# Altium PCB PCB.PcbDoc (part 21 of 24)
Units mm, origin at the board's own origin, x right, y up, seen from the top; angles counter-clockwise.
Board outline 100 x 160 mm, 10 copper layers (TOP_L1, L2, L3, L4, L5, L6, L7, L8, L9, BOTTOM_L10), stack 1.946 mm thick; 1358 components, 1149 nets, 6777 pads, 10914 vias.
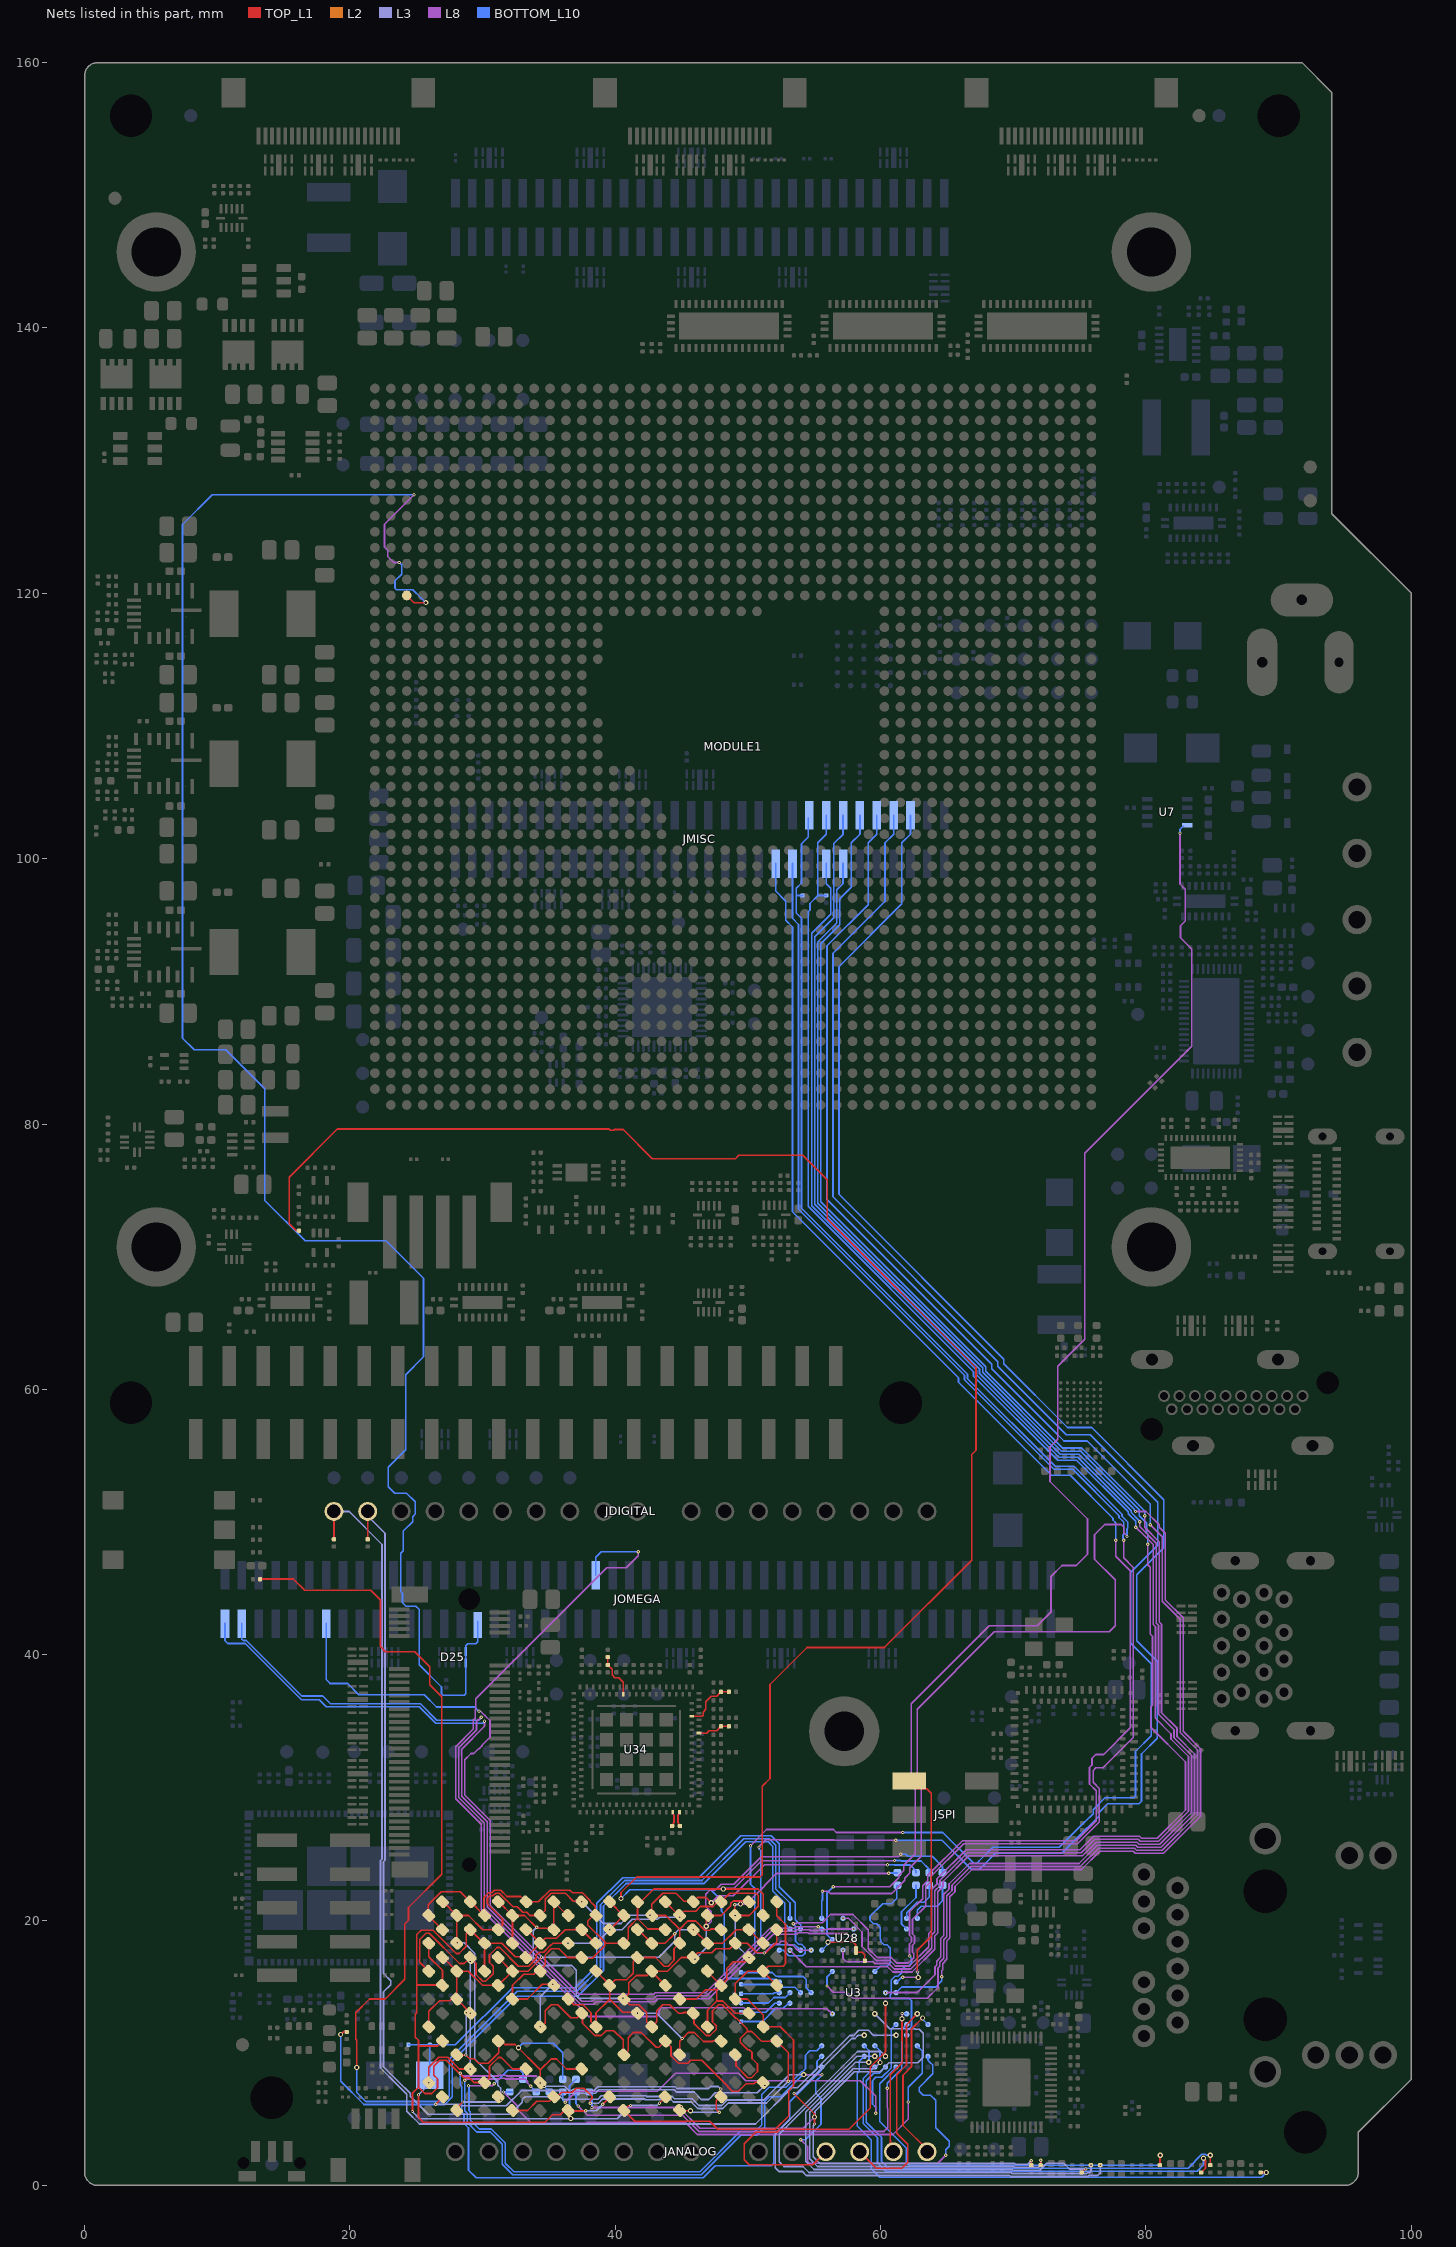
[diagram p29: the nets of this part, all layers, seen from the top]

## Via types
v1: diameter 0.25, hole 0.1, TOP_L1 to L2, tented both sides, 3439 vias
v2: diameter 0.25, hole 0.1, L2 to L3, tented both sides, 2256 vias
v3: diameter 0.25, hole 0.1, L9 to BOTTOM_L10, tented both sides, 1685 vias
v4: diameter 0.25, hole 0.1, L8 to L9, tented both sides, 1675 vias
v5: diameter 0.4, hole 0.2, L3 to L8, tented both sides, 1251 vias
v6: diameter 0.6, hole 0.3, TOP_L1 to BOTTOM_L10, tented both sides, 600 vias
v7: diameter 0.24, hole 0.1, TOP_L1 to L2, tented both sides, 8 vias

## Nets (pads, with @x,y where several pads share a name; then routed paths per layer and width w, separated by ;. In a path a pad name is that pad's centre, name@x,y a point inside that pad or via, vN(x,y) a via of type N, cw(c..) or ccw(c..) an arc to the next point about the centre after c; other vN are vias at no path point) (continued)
PE4: JMISC.6 U3.C4 | length 132.4
  L8 w0.127: v3(50.834,25.477) 50.834,25.51 50.898,25.574 50.898,25.596 51.345,26.043 52.351,26.043 52.362,26.031 56.51,26.031 56.52,26.021 v4(61.138,26.021)
  BOTTOM_L10 w0.127: v3(50.834,25.477) 50.858,25.453 50.858,25.348 50.96,25.246 50.96,18.492 51.303,18.149 53.508,18.149 53.719,17.938 53.754,17.938 U3.C4@53.963,17.729 ; v4(61.138,26.021) 64.62,26.021 66.823,23.818 67.438,23.818 67.873,24.253 67.873,24.258 68.642,25.028 73.65,25.028 75.576,26.955 75.593,26.955 76.476,27.837 76.476,28.138 77.098,28.76 79.467,28.76 79.666,28.958 79.666,32.516 80.841,33.691 80.841,39.504 79.3,41.046 79.3,46.022 81.34,48.062 81.34,51.689 75.903,57.126 74.086,57.126 69.273,61.939 69.273,62.278 56.858,74.694 56.858,91.849 61.601,96.592 61.601,101.19 62.249,101.838 JMISC.6@62.249,103.277
  other v3: 61.138,26.021
  other v4: 50.834,25.477
PE5: JMISC.8 U3.D4 | length 134.9
  L8 w0.127: v3(50.188,25.609) 51.403,26.824 56.444,26.824 56.662,26.605 61.652,26.605 v3(61.66,26.597) ; v4(51.223,17.516) 51.907,18.2 52.32,18.2 52.513,18.392 52.814,18.392 53.09,18.116 53.353,18.116 53.74,17.729 v3(54.763,17.729)
  BOTTOM_L10 w0.127: v3(50.188,25.609) 50.188,22.712 50.506,22.395 50.506,17.73 50.72,17.516 v4(51.223,17.516) ; JMISC.8@60.979,103.277 60.979,101.838 60.331,101.19 60.331,96.791 56.404,92.864 56.404,74.506 68.819,62.09 68.819,61.751 72.676,57.894 73.57,57 73.981,56.589 75.799,56.589 80.886,51.501 80.886,48.25 78.846,46.21 78.846,40.858 80.387,39.316 80.387,33.879 79.212,32.704 79.212,29.325 79.101,29.214 76.91,29.214 76.022,28.326 76.022,28.025 75.405,27.409 75.388,27.409 73.462,25.482 68.454,25.482 67.419,24.446 67.419,24.441 67.25,24.272 67.011,24.272 64.688,26.595 61.662,26.595 v3(61.66,26.597)
  other v3: 51.223,17.516
  other v4: 54.763,17.729 50.188,25.609 61.66,26.597
PE6: JMISC.10 U3.F6 | length 128.8
  L8 w0.127: v4(55.963,15.029) 56.431,14.561 57.452,14.561 57.913,14.1 63.507,14.1 64.322,14.915 64.322,16.383 64.445,16.506 64.445,16.814 64.76,17.128 64.76,18.512 64.987,18.739 64.987,21.843 65.376,22.232 65.376,22.621 66.793,24.039 75.05,24.039 76.428,25.417 79.128,25.417 79.282,25.264 81.23,25.264 83.886,27.92 83.886,32.816 82.57,34.132 82.57,42.682 81.232,44.02 81.232,48.882 v3(80.32,49.794)
  BOTTOM_L10 w0.127: v4(55.963,15.029) 55.963,15.729 U3.F6@56.363,16.129 ; JMISC.10@59.709,103.277 59.709,101.838 59.061,101.19 59.061,96.521 55.95,93.41 55.95,74.318 68.365,61.902 68.365,61.563 72.676,57.252 72.928,57 73.823,56.105 75.577,56.105 80.32,51.362 v3(80.32,49.794)
  other v3: 55.963,15.029
  other v4: 80.32,49.794
PE7: JMISC.12 U3.L8 | length 121.4
  L8 w0.127: v4(60.363,14.529) 60.38,14.546 62.764,14.546 64.095,15.877 64.095,16.477 64.218,16.6 64.218,16.908 64.533,17.222 64.533,18.606 64.76,18.833 64.76,21.937 65.149,22.326 65.149,22.715 66.699,24.266 74.956,24.266 76.334,25.644 79.223,25.644 79.376,25.491 81.136,25.491 83.659,28.014 83.659,32.519 82.343,33.836 82.343,34.447 81.171,35.619 81.171,42.302 81.005,42.469 81.005,48.497 79.904,49.597 v3(79.904,50.477)
  BOTTOM_L10 w0.127: JMISC.12@58.439,103.277 58.439,101.838 57.791,101.19 57.791,97.85 56.925,96.984 56.925,95.027 55.496,93.598 55.496,74.13 67.911,61.714 67.911,61.374 73.7,55.586 75.144,55.586 79.904,50.826 v3(79.904,50.477)
  other v3: 60.363,14.529
  other v4: 79.904,50.477
PE8: JMISC.14 U3.M8 | length 121.8
  L8 w0.127: v3(64.611,15.716) 64.611,16.204 64.672,16.265 64.672,16.72 64.987,17.034 64.987,18.418 65.214,18.645 65.214,21.749 65.603,22.138 65.603,22.527 66.887,23.812 75.144,23.812 76.522,25.19 79.034,25.19 79.188,25.037 81.324,25.037 84.113,27.826 84.113,32.91 82.797,34.226 82.797,42.785 81.459,44.123 81.459,49.146 80.99,49.614 80.99,49.799 79.996,50.794 v3(79.207,50.794)
  BOTTOM_L10 w0.127: JMISC.14@57.169,103.277 57.169,101.838 56.471,101.14 56.471,95.55 55.042,94.121 55.042,73.941 67.457,61.526 67.457,61.186 73.535,55.108 74.949,55.108 79.104,50.953 79.104,50.93 79.207,50.827 v3(79.207,50.794) ; U3.M8@61.163,14.529 61.583,14.949 64.141,14.949 64.611,15.419 v3(64.611,15.716)
  other v4: 64.611,15.716 79.207,50.794
PE12: JANALOG.11 U3.L9 | length 26.9
  TOP_L1 w0.127: JANALOG.11@55.88,2.54 54.893,1.553 50.089,1.553 49.713,1.929 49.713,3.129 50.586,4.002 52.157,4.002 52.384,4.229 57.613,4.229 59.213,5.829 59.213,8.929 60.363,10.079 v2(60.363,13.729)
  other v1: 60.363,13.729
  other v3: 60.363,13.729
  other v4: 60.363,13.729
  other v5: 60.363,13.729
PE13: JANALOG.12 U3.P10 | length 16.5
  TOP_L1 w0.127: JANALOG.12@58.42,2.54 59.657,1.303 61.587,1.303 62.033,1.749 62.033,3.098 61.206,3.926 61.206,8.337 61.949,9.079 61.949,12.114 v1(62.763,12.929)
  other v2: 62.763,12.929
  other v3: 62.763,12.929
  other v4: 62.763,12.929
  other v5: 62.763,12.929
PE14: JANALOG.13 U3.N10 | length 11.3
  TOP_L1 w0.127: JANALOG.13@60.96,2.54 60.74,2.76 60.74,3.342 60.733,3.349 60.733,8.345 61.631,9.242 61.631,10.87 61.606,10.894 v1(61.606,12.558)
  L8 w0.127: v1(61.606,12.558) 61.617,12.568 61.617,12.951 v3(61.627,12.961)
  BOTTOM_L10 w0.127: v3(61.627,12.961) 61.659,12.929 U3.N10@61.963,12.929
  other v2: 61.606,12.558
  other v4: 61.627,12.961
  other v5: 61.606,12.558
PE15: JANALOG.14 U3.R11 | length 12.1
  TOP_L1 w0.127: v5(63.161,12.616) v5(63.161,12.616) 62.319,11.776 62.319,8.944 61.681,8.306 61.681,4.522 63.5,2.703 JANALOG.14@63.5,2.54
  BOTTOM_L10 w0.127: v5(63.161,12.616) 63.184,12.592 63.184,12.509 U3.R11@63.563,12.13
  other v1: 63.161,12.616
  other v2: 63.161,12.616
  other v3: 63.161,12.616
  other v4: 63.161,12.616
PET_CAP_25_N: C327.1 U34.A7 | length 1.1
  TOP_L1 w0.122: C327.1@44.275,27.102 44.279,27.102 44.372,27.195 44.372,27.289 44.422,27.339 44.422,27.896 44.38,27.937 44.38,28.09 U34.A7@44.341,28.129
PET_CAP_25_P: C326.1 U34.A5 | length 1.1
  TOP_L1 w0.122: U34.A5@44.841,28.129 44.841,28.054 44.727,27.939 44.727,27.34 44.778,27.288 44.778,27.195 44.871,27.102 C326.1@44.875,27.102
PF0: JMISC.18 R373.1 U3.E1 | length 117
  L8 w0.127: v4(55.611,22.181) 56.028,22.181 56.209,22 57.828,22 57.834,22.006 60.825,22.006 61.809,22.99 61.809,23.16 62.198,23.549 62.198,23.938 63.063,24.803 63.063,30.323 62.753,30.633 62.753,35.899 68.575,41.721 77.235,41.721 77.687,42.173 77.687,45.643 76.123,47.207 76.123,49.039 76.9,49.816 78.131,49.816 78.311,49.635 78.311,49.199 78.562,48.949 v3(78.562,48.916)
  BOTTOM_L10 w0.127: R373.1@54.109,97.228 53.642,97.228 53.641,97.229 ; JMISC.18@54.541,103.075 54.541,101.635 54.034,101.129 54.034,98.168 53.641,97.775 53.641,97.229 ; U3.E1@55.563,20.129 55.563,21.445 55.611,21.493 v4(55.611,22.181) ; v3(78.562,48.916) 78.562,49.489 78.623,49.55 78.623,50.007 78.196,50.434 78.196,50.577 74.573,54.2 73.159,54.2 66.549,60.81 66.549,61.15 54.041,73.659 54.041,95.501 53.641,95.901 53.641,97.229
  other v3: 55.611,22.181
  other v4: 78.562,48.916
PF1: JMISC.16 R374.1 U3.G4 | length 123.7
  L8 w0.127: v4(57.163,17.729) 57.163,17.114 57.385,16.892 57.422,16.855 57.475,16.855 57.927,16.858 ; 57.928,16.858 59.425,16.858 59.563,16.719 60.608,16.719 61.02,16.308 62.273,16.308 63.852,17.887 63.852,18.888 64.079,19.115 64.079,22.219 64.468,22.608 64.468,22.998 66.547,25.076 75.124,25.076 76.146,26.098 79.411,26.098 79.564,25.945 80.948,25.945 83.205,28.202 83.205,32.331 81.889,33.648 81.889,34.026 80.692,35.224 80.692,36.061 80.717,36.086 80.717,42.114 80.551,42.281 80.551,48.309 79.955,48.904 79.934,48.904 v3(79.223,49.616)
  BOTTOM_L10 w0.127: R374.1@55.899,97.228 55.273,97.228 55.251,97.207 ; JMISC.16@55.899,103.277 55.899,101.838 55.251,101.19 55.251,97.207 ; v3(79.223,49.616) 79.223,50.049 78.65,50.622 78.65,50.765 74.761,54.654 73.347,54.654 67.003,60.998 67.003,61.338 54.542,73.799 54.542,96.004 54.67,96.131 54.67,96.625 55.251,97.207
  other v3: 57.163,17.729
  other v4: 79.223,49.616
PF4: JMISC.13 U3.G1 | length 120.1
  L8 w0.127: v3(57.163,20.129) 57.571,20.129 58.595,19.105 58.595,18.009 59.657,16.946 60.702,16.946 61.114,16.535 62.179,16.535 63.625,17.981 63.625,18.982 63.852,19.209 63.852,22.313 64.241,22.702 64.241,23.092 66.452,25.303 75.03,25.303 76.052,26.325 79.505,26.325 79.658,26.172 80.854,26.172 82.978,28.296 82.978,31.908 80.363,34.522 80.363,36.053 80.49,36.18 80.49,41.393 80.324,41.559 80.324,46.583 80.123,46.784 v4(80.123,48.316)
  BOTTOM_L10 w0.127: JMISC.13@57.169,99.629 57.169,98.128 56.698,97.658 56.698,95.15 55.269,93.721 55.269,74.035 67.684,61.62 67.684,61.28 73.629,55.335 75.074,55.335 79.496,50.913 79.496,50.478 80.031,49.942 80.031,49.191 80.123,49.1 v4(80.123,48.316)
  other v3: 80.123,48.316
  other v4: 57.163,20.129
PF6: JOMEGA.98 U3.H3 | length 71
  L8 w0.127: v4(29.889,35.292) 29.533,34.935 29.533,34.305 28.204,32.976 28.204,29.235 30.12,27.318 30.12,20.914 37.381,13.653 38.375,13.653 38.557,13.835 42.971,13.835 43.198,14.062 45.592,14.062 45.604,14.074 47.045,14.074 51.898,18.927 53.684,18.927 53.795,19.038 54.524,19.038 54.573,18.989 57.503,18.989 v3(57.963,18.529)
  BOTTOM_L10 w0.127: JOMEGA.98@11.856,42.35 11.856,41.175 11.965,41.067 12.193,41.067 16.375,36.885 17.953,36.885 18.536,36.303 25.323,36.303 26.554,35.072 29.714,35.072 29.826,35.183 29.826,35.195 29.889,35.258 v4(29.889,35.292)
  other v3: 29.889,35.292
  other v4: 57.963,18.529
PF7: JOMEGA.100 U3.H2 | length 71.8
  L8 w0.127: v3(30.148,34.992) 30.148,34.599 28.431,32.882 28.431,29.329 30.347,27.413 30.347,21.008 37.475,13.88 38.281,13.88 38.463,14.062 42.877,14.062 43.104,14.289 45.498,14.289 45.51,14.301 46.897,14.301 51.749,19.154 53.59,19.154 53.701,19.265 54.618,19.265 54.667,19.216 55.406,19.216 55.455,19.265 55.907,19.265 55.971,19.329 v4(57.963,19.329)
  BOTTOM_L10 w0.127: JOMEGA.100@10.586,42.35 10.586,41.056 10.802,40.84 12.099,40.84 16.345,36.594 17.685,36.594 18.203,36.076 25.229,36.076 26.46,34.845 30.001,34.845 v3(30.148,34.992)
  other v3: 57.963,19.329
  other v4: 30.148,34.992
PF14: JSPI.1 U3.M7 | length 18.2
  TOP_L1 w0.1: JSPI.1@62.167,30.48 62.752,29.895 63.491,29.895 63.823,29.562 63.823,18.775 62.775,17.726 v2(62.775,16.081)
  L3 w0.1: v2(62.775,16.081) 62.799,16.057 62.799,15.699 v5(62.823,15.675)
  L8 w0.1: v4(61.677,15.7) 61.702,15.675 v5(62.823,15.675)
  BOTTOM_L10 w0.1: U3.M7@61.163,15.329 61.233,15.329 61.575,15.671 61.648,15.671 v4(61.677,15.7)
  other v1: 62.775,16.081
  other v3: 61.677,15.7
PG2: R205_1.2 U3.L15 | length 34.6
  TOP_L1 w0.127: v3(84.847,2.285) 84.849,2.283 84.849,1.526 R205_1.2@84.85,1.525
  BOTTOM_L10 w0.127: U3.L15@60.363,8.929 59.883,8.449 59.484,8.449 58.921,7.886 58.921,4.76 60.059,3.621 60.059,1.81 60.565,1.304 83.176,1.304 84.215,2.344 84.485,2.344 84.544,2.285 v3(84.847,2.285)
  other v1: 84.847,2.285
  other v2: 84.847,2.285
  other v4: 84.847,2.285
  other v5: 84.847,2.285
PG3: R205_4.2 U3.J12 | length 29.7
  TOP_L1 w0.127: v1(53.463,6.929) 55.013,5.379 v2(55.013,4.629) ; R205_4.2@71.35,1.525 71.35,1.862 v1(71.353,1.865)
  L3 w0.127: v1(53.463,6.929) 53.484,6.95 53.688,6.95 57.81,11.072 58.063,11.072 58.32,11.329 v3(58.763,11.329) ; v2(55.013,4.629) 55.013,4.596 54.919,4.502 54.919,2.152 55.418,1.653 70.114,1.653 70.171,1.595 71.084,1.595 v1(71.353,1.865)
  other v1: 55.013,4.629
  other v2: 71.353,1.865 53.463,6.929
  other v4: 58.763,11.329
  other v5: 58.763,11.329
PG4: R205_3.2 U3.K14 | length 36.1
  L3 w0.127: v3(59.563,9.729) 58.219,9.729 52.368,3.878 52.368,1.772 52.715,1.425 54.15,1.425 54.603,0.972 69.832,0.972 69.903,0.901 75.529,0.901 75.601,0.972 75.776,0.972 75.85,1.046 v2(75.85,1.525)
  other v1: 75.85,1.525
  other v4: 59.563,9.729
  other v5: 59.563,9.729
PG5: R208_2.2 U3.K15 | length 34.8
  TOP_L1 w0.127: R208_2.2@84.15,0.975 84.165,0.975 84.484,1.293 84.484,1.886 84.334,2.036 v3(84.334,2.055)
  BOTTOM_L10 w0.127: U3.K15@59.563,8.929 58.694,8.06 58.694,4.666 59.759,3.6 59.759,1.71 60.392,1.077 83.863,1.077 84.334,1.548 v3(84.334,2.055)
  other v1: 84.334,2.055
  other v2: 84.334,2.055
  other v4: 84.334,2.055
  other v5: 84.334,2.055
PG6: R208_4.2 U3.J13 | length 33.6
  TOP_L1 w0.127: R208_4.2@75.15,0.975 75.174,0.975 75.443,1.244 v1(75.464,1.244)
  L3 w0.127: v5(59.092,9.29) 58.101,9.29 54.35,5.539 54.35,1.825 54.976,1.199 69.926,1.199 69.983,1.141 71.988,1.141 72.51,1.663 73.811,1.663 74.233,1.242 75.463,1.242 v1(75.464,1.244)
  BOTTOM_L10 w0.127: U3.J13@58.763,10.529 59.127,10.165 59.127,9.358 59.092,9.324 v5(59.092,9.29)
  other v2: 75.464,1.244
  other v3: 59.092,9.29
  other v4: 59.092,9.29
PG8: R208_1.2 U3.J14 | length 39.7
  TOP_L1 w0.127: R208_1.2@88.65,0.975 v3(89.064,0.975)
  BOTTOM_L10 w0.127: U3.J14@58.763,9.729 58.391,9.357 58.391,8.6 58.24,8.449 58.24,4.478 59.295,3.423 59.295,1.273 59.944,0.623 88.715,0.623 89.064,0.973 v3(89.064,0.975)
  other v1: 89.064,0.975
  other v2: 89.064,0.975
  other v4: 89.064,0.975
  other v5: 89.064,0.975
PG9: R365.1 U3.B9 | length 4.2
  BOTTOM_L10 w0.127: R365.1@49.486,12.349 51.104,12.349 52.099,13.344 52.663,13.344 52.957,13.637 52.997,13.637 53.089,13.729 U3.B9@53.163,13.729
PG10: R366.1 U3.A9 | length 3.1
  BOTTOM_L10 w0.127: R366.1@49.531,13.049 51.34,13.049 52.02,13.729 U3.A9@52.363,13.729
PG11: R408.1 U3.D8 | length 6.3
  BOTTOM_L10 w0.127: R408.1@49.486,16.049 51.831,16.049 52.109,15.771 52.242,15.771 52.269,15.744 54.165,15.744 54.389,15.52 54.389,14.903 U3.D8@54.763,14.529
PG12: R409.1 U3.C8 | length 4.7
  BOTTOM_L10 w0.127: R409.1@49.531,15.149 52.029,15.149 52.232,14.946 53.546,14.946 U3.C8@53.963,14.529
PG13: R410.1 U3.B8 | length 4
  BOTTOM_L10 w0.127: R410.1@49.531,13.749 51.54,13.749 51.957,14.165 52.8,14.165 U3.B8@53.163,14.529
PG14: R411.1 U3.A8 | length 2.9
  BOTTOM_L10 w0.127: R411.1@49.531,14.449 51.909,14.449 51.989,14.529 U3.A8@52.363,14.529
PG15: R264.2 U3.A7 | length 145.4
  TOP_L1 w0.127: R264.2@16.16,71.95 15.95,71.95 15.415,72.485 15.415,75.996 19.047,79.628 39.533,79.628 39.632,79.529 39.871,79.529 39.925,79.583 40.596,79.583 42.792,77.386 49.059,77.386 49.315,77.642 54.131,77.642 55.977,75.796 55.977,73.072 55.977,72.865 67.189,61.653 67.189,55.419 66.861,55.092 66.861,47.122 60.284,40.545 54.452,40.545 51.657,37.75 51.657,30.665 51.066,30.073 51.066,23.412 50.904,23.25 41.609,23.25 40.435,22.075 v2(40.435,21.628)
  BOTTOM_L10 w0.127: v2(40.435,21.628) 41.102,22.296 47.197,22.296 48.008,21.484 48.008,20.667 48.224,20.452 48.224,15.916 48.54,15.6 51.648,15.6 51.704,15.544 52.148,15.544 U3.A7@52.363,15.329
  other v1: 40.435,21.628
  other v3: 40.435,21.628
  other v4: 40.435,21.628
  other v5: 40.435,21.628
PH2: R108.2 U3.N1 | length 3.5
  BOTTOM_L10 w0.127: U3.N1@61.963,20.129 61.963,20.542 62.765,21.344 63.265,21.344 63.665,21.744 R108.2@63.665,22.625
PH3: R195.2 U3.N2 | length 3.9
  BOTTOM_L10 w0.127: U3.N2@61.963,19.329 61.565,19.727 61.565,20.605 62.665,21.705 R195.2@62.665,22.625
PH4: R196.2 U3.P1 | length 4
  BOTTOM_L10 w0.127: U3.P1@62.763,20.129 62.763,20.742 63.065,21.044 64.265,21.044 64.665,21.444 R196.2@64.665,22.625
PH5: R197.2 U3.K6 | length 9.4
  BOTTOM_L10 w0.127: U3.K6@59.563,16.129 59.963,16.529 60.477,16.529 60.727,16.778 60.727,17.88 60.477,18.129 60.249,18.129 60,18.378 60,18.529 ; 59.963,18.529 59.963,19.443 59.695,19.711 59.467,19.711 59.2,19.978 59.2,20.28 60.149,21.229 60.815,21.229 61.215,21.629 61.215,22.575 R197.2@61.265,22.625
PH6: R198.2 U3.N11 | length 33.8
  L8 w0.127: v3(37.216,5.979) 37.911,5.284 45.065,5.284 46.279,4.07 60.256,4.07 60.537,4.35 60.537,5.793 60.49,5.839 v3(60.49,7.315)
  BOTTOM_L10 w0.127: R198.2@37.039,7.048 37.039,6.156 v3(37.216,5.979) ; v3(60.49,7.315) 60.49,7.692 61.593,8.795 61.593,11.758 U3.N11@61.963,12.129
  other v4: 37.216,5.979 60.49,7.315
PH7: R199.2 U3.M11 | length 35
  L8 w0.127: v3(36.221,6.268) 37.054,7.1 43.186,7.1 44.535,8.449 49.281,8.449 49.832,7.898 58.466,7.898 59.623,6.741 v3(59.623,5.433)
  BOTTOM_L10 w0.127: R199.2@36.039,7.048 36.039,6.45 v3(36.221,6.268) ; v3(59.623,5.433) 59.623,5.898 59.39,6.131 59.39,7.899 59.633,8.142 60.091,8.142 60.795,8.847 60.795,11.761 U3.M11@61.163,12.129
  other v4: 59.623,5.433 36.221,6.268
PH8: JMISC.21 U3.N12 | length 115.6
  L8 w0.127: v3(62.204,17.289) 62.18,17.312 62.18,17.477 62.173,17.484 62.173,18.201 62.327,18.355 62.327,18.699 62.173,18.853 62.173,20.603 63.171,21.601 63.171,22.595 63.56,22.984 63.56,23.374 66.17,25.984 74.748,25.984 76.25,27.487 76.25,29.748 75.747,30.251 75.747,31.498 75.923,31.675 75.923,32.175 76.223,32.475 76.811,32.475 78.822,34.486 78.822,46.316 77.723,47.416 v3(77.723,48.616)
  BOTTOM_L10 w0.127: JMISC.21@52.089,99.629 52.089,97.56 52.85,96.799 52.85,95.363 53.36,94.853 53.36,73.377 65.868,60.868 65.868,60.528 72.877,53.519 74.291,53.519 77.515,50.295 77.515,50.152 77.723,49.944 v3(77.723,48.616) ; U3.N12@61.963,11.329 61.963,11.633 62.096,11.765 62.114,11.765 62.327,11.978 62.327,13.912 62.146,14.092 60.788,14.092 60.713,14.167 60.713,14.365 60.8,14.451 60.8,15.48 61.086,15.765 61.314,15.765 61.581,16.033 61.581,16.261 61.849,16.529 62.077,16.529 62.327,16.778 62.327,17.132 62.204,17.255 v3(62.204,17.289)
  other v4: 62.204,17.289 77.723,48.616
PH9: R200.2 U3.P13 | length 39.3
  L8 w0.127: v4(31.568,7.036) 32.639,5.965 32.639,5.725 33.686,4.677 37.85,4.677 37.926,4.753 45.275,4.753 46.185,3.843 60.929,3.843 62.09,5.004 v3(62.09,6.284)
  BOTTOM_L10 w0.127: v4(31.568,7.036) 31.574,7.042 32.216,7.042 R200.2@32.222,7.036 ; v3(62.09,6.284) 62.09,7.409 63.127,8.446 63.127,10.13 62.763,10.494 U3.P13@62.763,10.529
  other v3: 31.568,7.036
  other v4: 62.09,6.284
PH10: R201.2 U3.K10 | length 35.3
  L3 w0.127: v5(55.01,5.152) 55.052,5.194 55.052,5.599 58.019,8.566 59.954,8.566 60.631,9.242 62.79,9.242 63.2,9.651 63.2,11.48 62.914,11.765 62.613,11.765 62.578,11.8 60.692,11.8 v3(59.563,12.929)
  L8 w0.127: v4(38.238,5.867) 44.803,5.867 46.373,4.297 54.155,4.297 v5(55.01,5.152)
  BOTTOM_L10 w0.127: v4(38.238,5.867) 38.239,5.868 R201.2@38.239,7.048
  other v3: 38.238,5.867
  other v4: 59.563,12.929
  other v5: 59.563,12.929
PH11: JDIGITAL.18 R372.1 U3.M12 | length 90.7
  TOP_L1 w0.127: R372.1@18.796,48.7 JDIGITAL.18@18.796,50.8
  L3 w0.127: JDIGITAL.18@18.796,50.8 19.924,50.8 22.413,48.311 22.413,24.598 22.304,24.49 22.304,8.846 23.528,7.622 24.288,6.862 24.288,5.587 25.241,4.634 50.568,4.634 53.3,7.365 53.733,7.365 57.667,11.299 57.969,11.299 58.362,11.692 59.089,11.692 59.452,11.329 v3(61.163,11.329)
  other v4: 61.163,11.329
  other v5: 61.163,11.329
PH12: JDIGITAL.17 R371.1 U3.R14 | length 109.9
  TOP_L1 w0.127: R371.1@21.336,48.7 JDIGITAL.17@21.336,50.8
  L3 w0.127: JDIGITAL.17@21.336,50.8 21.336,50.449 22.64,49.146 22.64,24.504 22.531,24.396 22.531,15.975 23.069,15.437 23.069,15.136 22.531,14.598 22.531,8.94 23.622,7.849 24.535,6.937 24.535,6.728 25.898,5.366 32.1,5.366 32.998,6.264 32.998,6.481 33.211,6.693 35.851,6.693 36.055,6.49 38.695,6.49 38.952,6.747 42.31,6.747 42.362,6.695 43.165,6.695 43.173,6.703 44.294,6.703 44.46,6.537 45.788,6.537 46.303,6.022 48.014,6.022 48.428,6.437 51.19,6.437 53.106,8.353 v5(54.194,8.353)
  L8 w0.127: v3(53.987,3.437) 54.486,2.938 54.486,1.814 54.635,1.665 64.31,1.665 64.914,2.27 v3(64.914,2.274) ; v5(54.194,8.353) 54.2,8.347 55.575,8.347 v3(55.582,8.341)
  BOTTOM_L10 w0.127: v3(53.987,3.437) 54.318,3.437 55.5,4.619 55.5,6.581 55.118,6.963 55.118,7.846 55.582,8.31 v3(55.582,8.341) ; U3.R14@63.563,9.729 63.563,9.425 63.696,9.292 63.714,9.292 63.927,9.08 63.927,8.41 62.9,7.383 62.9,7.1 63.2,6.8 63.761,6.8 64.144,6.418 64.144,4.348 65.167,3.324 65.167,2.943 64.914,2.691 v3(64.914,2.274)
  other v4: 64.914,2.274 53.987,3.437 55.582,8.341
PH13: R202.2 U3.E15 | length 47.6
  L8 w0.127: v4(28.316,8.451) 28.516,8.251 31.2,8.251 31.251,8.302 31.74,8.302 31.791,8.251 34.022,8.251 34.634,7.639 v3(34.634,7.458)
  BOTTOM_L10 w0.127: v3@28.311,8.445 28.311,7.574 28.425,7.46 28.425,5.534 28.604,5.355 28.604,4.668 28.939,4.332 28.939,1.153 29.516,0.576 46.622,0.576 47.529,1.483 51.769,1.483 51.955,1.669 51.955,3.8 53.139,4.984 53.139,6.306 55.511,8.678 55.511,8.872 U3.E15@55.563,8.924 ; v3(34.634,7.458) 35.044,7.048 R202.2@35.225,7.048
  other v3: 28.316,8.451
  other v4: 34.634,7.458
PH14: R203.2 U3.E14 | length 43.9
  L8 w0.127: v3(28.652,7.917) 28.685,7.917 28.788,8.021 31.29,8.021 31.345,8.075 31.646,8.075 31.7,8.021 33.204,8.021 33.384,7.841 33.384,7.723 v4(33.633,7.474)
  BOTTOM_L10 w0.127: v3(28.652,7.917) 28.652,5.628 28.831,5.449 28.831,4.762 29.566,4.026 30.563,4.026 31.488,3.101 31.488,1.583 32.268,0.803 46.477,0.803 49.481,3.807 50.693,3.807 51.266,4.38 51.266,6.347 51.595,6.675 52.466,6.675 54.129,8.338 54.794,8.338 55.2,8.744 55.2,9.366 U3.E14@55.563,9.729 ; v4(33.633,7.474) 33.633,7.456 34.041,7.048 R203.2@34.239,7.048
  other v3: 33.633,7.474
  other v4: 28.652,7.917
PH15: R204.2 U3.E13 | length 42.7
  L8 w0.127: v4(28.94,7.518) 30.736,7.518 v3(30.885,7.666)
  BOTTOM_L10 w0.127: v4(28.94,7.518) 28.964,7.494 28.964,7.407 28.97,7.401 28.97,5.631 29.058,5.543 29.058,4.935 29.739,4.253 30.657,4.253 31.715,3.195 31.715,1.677 32.362,1.03 46.383,1.03 49.387,4.034 50.52,4.034 51.039,4.553 51.039,6.853 51.581,7.395 52.865,7.395 54.035,8.565 54.114,8.565 54.34,8.792 54.34,9.82 54.669,10.149 55.183,10.149 U3.E13@55.563,10.529 ; v3(30.885,7.666) 31.893,8.675 32.817,8.675 33.039,8.453 R204.2@33.039,7.998
  other v3: 28.94,7.518
  other v4: 30.885,7.666
PI2: JOMEGA.55 U3.F10 | length 69.5
  L8 w0.127: v3(41.733,47.749) 41.733,47.449 40.833,46.549 39.349,46.549 29.487,36.687 29.487,35.911 29.445,35.868 29.445,35.215 29.306,35.076 29.306,34.399 27.977,33.07 27.977,29.141 29.893,27.224 29.893,20.82 37.975,12.738 43.122,12.738 43.301,12.917 43.301,13.202 43.48,13.381 45.874,13.381 45.886,13.393 47.254,13.393 47.266,13.381 49.678,13.381 49.748,13.312 55.945,13.312 56.119,13.138 56.154,13.138 v4(56.363,12.929)
  BOTTOM_L10 w0.127: JOMEGA.55@38.526,46 38.526,47.342 38.933,47.749 v3(41.733,47.749)
  other v3: 56.363,12.929
  other v4: 41.733,47.749
PI5: JMISC.19 U3.A4 | length 123.5
  L8 w0.127: v3(53.423,19.716) 53.446,19.739 53.626,19.739 53.68,19.793 55.6,19.793 56.224,20.417 57.921,20.417 59.077,19.262 59.077,17.848 59.751,17.173 60.796,17.173 61.208,16.762 62.085,16.762 62.492,17.169 62.492,17.486 62.4,17.578 62.4,18.107 62.554,18.261 62.554,18.793 62.4,18.947 62.4,20.049 63.398,21.047 63.398,22.501 63.787,22.89 63.787,23.28 66.264,25.757 74.842,25.757 76.477,27.393 76.477,29.921 76.023,30.375 76.023,31.275 76.223,31.475 76.759,31.475 79.049,33.765 79.049,46.571 78.323,47.297 v3(78.323,48.616)
  BOTTOM_L10 w0.127: U3.A4@52.363,17.729 52.667,17.729 52.8,17.596 52.8,17.578 53.069,17.309 54.116,17.309 54.293,17.487 54.293,17.545 54.327,17.578 54.327,17.88 54.041,18.165 53.813,18.165 53.577,18.402 53.577,19.529 53.423,19.683 v3(53.423,19.716) ; JMISC.19@53.359,99.629 53.359,95.496 53.814,95.041 53.814,73.565 66.322,61.056 66.322,60.716 73.065,53.973 74.479,53.973 77.969,50.483 77.969,50.34 78.311,49.998 78.311,49.085 78.273,49.047 78.273,48.796 78.299,48.77 78.299,48.639 v3(78.323,48.616)
  other v4: 53.423,19.716 78.323,48.616
PI7: JMISC.15 U3.B4 | length 123.6
  L8 w0.127: v3(53.163,17.729) 54.4,16.492 58.914,16.492 60.514,16.492 60.925,16.081 62.367,16.081 64.079,17.793 64.079,18.794 64.306,19.021 64.306,22.125 64.695,22.514 64.695,22.904 66.641,24.849 75.218,24.849 76.24,25.871 79.317,25.871 79.47,25.718 81.042,25.718 83.432,28.108 83.432,32.425 82.116,33.742 82.116,34.353 80.944,35.525 80.944,42.208 80.778,42.375 80.778,48.403 79.523,49.658 v4(79.523,50.016)
  BOTTOM_L10 w0.127: JMISC.15@55.899,99.629 55.899,98.117 56.244,97.772 56.244,95.813 54.815,94.384 54.815,73.847 67.23,61.432 67.23,61.092 73.441,54.881 74.855,54.881 78.877,50.859 78.877,50.716 79.45,50.143 79.45,50.122 79.523,50.049 v4(79.523,50.016)
  other v3: 79.523,50.016
  other v4: 53.163,17.729
PI8: R184.2 U3.E4 U28.6 | length 4.6
  TOP_L1 w0.127: v2(56.03,18.337) 57.93,18.337 58.133,18.134 58.133,17.66 58.219,17.575 58.623,17.575 58.813,17.385 R184.2@58.813,17.029
  L8 w0.127: v3(55.978,18.285) v2(56.03,18.337)
  BOTTOM_L10 w0.127: U3.E4@55.563,17.729 55.954,18.12 55.954,18.261 v3(55.978,18.285)
  other v1: 56.03,18.337
  other v4: 55.978,18.285
  other v5: 56.03,18.337
PI9: JOMEGA.88 U3.E2 | length 63.5
  L8 w0.127: v3(29.733,35.749) 29.84,35.749 30.178,35.411 30.552,35.037 30.552,33.772 29.957,33.177 29.957,33.126 29.744,32.913 29.693,32.913 29.336,32.556 29.122,32.556 28.658,32.092 28.658,29.423 30.574,27.507 30.574,21.102 37.275,14.402 42.896,14.402 43.01,14.516 45.404,14.516 45.416,14.528 46.803,14.528 51.664,19.389 53.504,19.389 53.62,19.505 v4(55.286,19.505)
  BOTTOM_L10 w0.127: JOMEGA.88@18.206,42.35 18.206,38.132 18.503,37.836 19.811,37.836 20.663,36.984 25.606,36.984 26.527,36.063 28.658,36.063 28.666,36.054 29.412,36.054 29.717,35.749 v3(29.733,35.749) ; v4(55.286,19.505) 55.32,19.505 55.495,19.329 U3.E2@55.563,19.329
  other v3: 55.286,19.505
  other v4: 29.733,35.749
PI11: U3.F3 U7.8 | length 104.1
  L8 w0.127: v4(56.423,22.516) 60.692,22.516 61.355,23.178 61.355,23.348 61.744,23.737 61.744,24.126 62.609,24.992 62.609,30.135 62.299,30.445 62.299,36.294 68.18,42.175 71.793,42.175 72.847,43.229 72.847,45.912 73.663,46.729 74.747,46.729 75.595,47.578 75.595,50.223 72.765,53.053 72.765,55.654 73.355,56.244 73.355,57 73.355,61 73.355,61.743 75.383,63.772 75.383,77.805 83.442,85.864 83.442,93.188 82.596,94.035 82.596,94.952 82.95,95.306 82.95,97.698 82.563,98.085 v4(82.563,101.925)
  BOTTOM_L10 w0.127: U3.F3@56.363,18.529 56.311,18.529 55.958,18.881 55.958,22.062 55.969,22.062 v4(56.423,22.516) ; v4(82.563,101.925) 82.563,102.213 82.79,102.44 U7.8@82.834,102.44
  other v3: 56.423,22.516 82.563,101.925
PK0: R207_2.1 U3.M15 | length 29.2
  TOP_L1 w0.127: R207_2.1@81.05,1.525 81.059,1.534 81.059,2.269 v4(81.067,2.278)
  BOTTOM_L10 w0.127: U3.M15@61.163,8.929 61.163,8.894 59.94,7.671 59.94,4.818 61.94,2.818 61.94,1.749 62.158,1.531 80.993,1.531 81.067,1.606 v4(81.067,2.278)
  other v1: 81.067,2.278
  other v2: 81.067,2.278
  other v3: 81.067,2.278
  other v5: 81.067,2.278
PK1: R207_3.1 U3.L14 | length 39.1
  L3 w0.127: v3(60.363,9.729) 60,10.092 58.261,10.092 52.05,3.881 52.05,1.325 52.319,1.056 54.093,1.056 54.404,0.745 69.738,0.745 69.809,0.674 75.623,0.674 75.695,0.745 76.37,0.745 76.55,0.925 v1(76.55,1.525)
  other v2: 76.55,1.525
  other v4: 60.363,9.729
  other v5: 60.363,9.729
PK2: R207_4.1 U3.K13 | length 30.3
  TOP_L1 w0.127: R207_4.1@72.05,1.525 72.059,1.534 v2(72.059,1.887)
  L3 w0.127: v3(59.958,9.269) 59.482,8.793 57.925,8.793 54.646,5.515 54.646,2.017 55.237,1.426 70.02,1.426 70.077,1.368 71.894,1.368 72.059,1.534 v2(72.059,1.887)
  BOTTOM_L10 w0.127: U3.K13@59.563,10.529 59.958,10.134 v3(59.958,9.269)
  other v1: 72.059,1.887
  other v4: 59.958,9.269
  other v5: 59.958,9.269
PK10: R484.2 U3.B2 | length 56.9
  TOP_L1 w0.127: v1(19.296,11.375) 19.329,11.375 19.529,11.575 R484.2@19.75,11.575
  BOTTOM_L10 w0.127: v1(19.296,11.375) 19.296,7.853 21.055,6.094 27.134,6.094 27.713,6.673 27.713,9.367 32.6,14.254 37.179,14.254 39.117,16.192 39.117,21.057 40.81,22.75 46.675,22.75 49.823,25.898 51.52,25.898 51.876,25.542 51.876,22.191 52.779,21.288 52.779,19.713 U3.B2@53.163,19.329
  other v2: 19.296,11.375
  other v3: 19.296,11.375
  other v4: 19.296,11.375
  other v5: 19.296,11.375
PK11: D44.A R510.1 R511.2 U3.C2 | length 46.7
  BOTTOM_L10 w0.109: R510.1@24.405,10.6 R511.2@26.03,10.6 ; D44.A@26.03,8.5 R511.2@26.03,10.6 ; U3.C2@53.963,19.329 53.963,19.633 53.822,19.774 53.816,19.774 53.55,20.041 53.55,21.307 52.359,22.498 52.359,25.742 51.751,26.35 49.45,26.35 46.3,23.2 40.55,23.2 38.6,21.25 38.6,16.52 36.989,14.909 32.259,14.909 27.95,10.6 R511.2@26.03,10.6
PK13: R482.2 U3.B1 | length 104.1
  TOP_L1 w0.127: R482.2@13.232,45.7 15.75,45.7 16.598,44.852 21.57,44.852 22.31,44.112 22.31,40.596 22.672,40.235 24.887,40.235 26.022,39.1 26.022,37.725 26.915,36.831 26.915,23.452 24.41,20.947 24.41,19.982 24.136,19.708 24.136,15.536 22.654,14.054 21.479,14.054 20.441,13.016 20.441,11.005 20.514,10.932 v5(20.514,8.889)
  BOTTOM_L10 w0.127: v5(20.514,8.889) 20.514,7.009 21.202,6.321 27.04,6.321 27.475,6.756 27.475,9.514 32.601,14.641 37.1,14.641 38.89,16.43 38.89,21.151 40.716,22.977 46.536,22.977 49.684,26.125 51.614,26.125 52.103,25.636 52.103,22.344 53.163,21.284 U3.B1@53.163,20.129
  other v1: 20.514,8.889
  other v2: 20.514,8.889
  other v3: 20.514,8.889
  other v4: 20.514,8.889
PL_512B_25: R287.1 R302.2 U34.AP22 | length 3.5
  TOP_L1 w0.1: R287.1@39.436,39.824 R302.2@39.436,39.224 39.766,38.894 39.766,38.476 39.968,38.275 40.256,38.275 40.591,37.94 U34.AP22@40.591,37.019
PM_PS_HOLD_1: D25.1 D25.10 JOMEGA.70 MODULE1.C33 | length 145.1
  TOP_L1 w0.127: MODULE1.C33@24.282,119.836 24.829,119.289 25.716,119.289 v4(25.726,119.299)
  L8 w0.127: v3(23.723,122.325) 23.302,122.325 22.856,122.77 22.856,123.234 22.608,123.482 22.608,125.209 v3(24.823,127.425)
  BOTTOM_L10 w0.127: v3(23.723,122.325) 23.899,122.15 23.899,121.448 23.402,120.951 23.402,120.368 23.514,120.257 24.735,120.257 25.352,119.64 25.385,119.64 v4(25.726,119.299) ; v3(24.823,127.425) 9.623,127.425 7.379,125.18 7.379,86.464 8.257,85.586 10.638,85.586 13.579,82.645 13.579,74.239 16.62,71.199 22.723,71.199 25.546,68.376 25.546,62.446 24.2,61.1 24.2,55.437 22.892,54.129 22.892,52.664 23.376,52.18 24.268,52.18 24.923,51.525 24.923,50.61 24.723,50.41 24.723,50.025 24.023,49.325 24.023,47.825 23.841,47.642 23.841,44.763 23.965,44.639 23.965,43.925 24.227,43.663 24.962,43.663 25.223,43.401 25.223,39.248 26.903,37.568 26.903,37.066 27.015,36.955 28.62,36.955 28.731,37.066 D25.1@28.731,39.374 D25.10@28.731,40.249 28.731,40.667 28.88,40.816 29.474,40.816 29.637,40.979 JOMEGA.70@29.637,42.514
  other v1: 25.726,119.299
  other v2: 25.726,119.299
  other v3: 25.726,119.299
  other v4: 23.723,122.325 24.823,127.425
  other v5: 25.726,119.299
PORTSTATUS_L1_SEL_25: R298.1 R307.2 U34.AC1 | length 2.5
  TOP_L1 w0.1: U34.AC1@46.311,34.099 46.885,34.099 47.055,34.269 47.631,34.269 R307.2@47.961,34.599 R298.1@48.561,34.599
PWR_SAV_25: R297.1 R306.2 U34.AH2 | length 4.1
  TOP_L1 w0.1: U34.AH2@45.761,35.349 46.549,35.349 46.636,35.437 46.636,35.675 46.834,35.872 46.834,36.461 47.242,36.869 47.631,36.869 R306.2@47.961,37.199 R297.1@48.561,37.199
ROW0_15: LED1.A LED2.C LED3.A LED4.C LED7.A LED8.C LED13.A LED14.C LED21.A LED22.C LED31.A LED32.C LED43.A LED44.C LED57.A LED58.C LED73.A LED74.C LED91.A LED92.C R108.1 | length 128.9
  TOP_L1 w0.127: v1(26.463,6.129) 26.973,6.639 LED92.C@26.973,6.675 ; LED14.C@26.973,19.275 25.947,20.301 LED1.A@25.947,20.35 25.894,20.403 25.894,21.147 26.876,22.129 28.319,22.129 LED2.C@29.073,21.375 29.097,21.375 LED3.A@30.07,20.403 ; LED3.A@30.147,20.35 30.094,20.403 30.094,21.694 30.449,22.048 30.678,22.048 30.883,22.253 31.356,22.253 31.835,21.775 32.874,21.775 33.281,21.367 33.79,21.367 33.798,21.375 34.205,21.375 35.083,22.253 36.579,22.253 36.774,22.058 37.53,22.058 38.124,21.465 38.124,21.404 38.494,21.033 38.494,20.489 LED7.A@38.356,20.35 ; LED31.A@34.294,16.203 34.722,16.63 34.722,17.371 35.177,17.826 35.758,17.826 36.409,17.175 37.049,17.175 37.058,17.184 37.464,17.184 LED32.C@37.473,17.175 37.526,17.122 38.266,17.122 39.199,18.055 39.199,18.206 ; v2(34.347,11.95) 34.423,11.95 34.722,12.249 34.722,13.171 35.177,13.626 35.672,13.626 36.651,12.648 37.145,12.648 LED58.C@37.473,12.975 37.526,12.922 37.526,12.231 38.458,11.299 38.946,11.299 39.315,11.667 39.894,11.667 40.594,10.967 40.594,9.903 LED73.A@40.647,9.85 40.972,10.175 40.972,11.138 41.361,11.526 41.966,11.526 43.09,10.403 43.3,10.403 LED74.C@43.773,10.875 44.196,10.452 44.196,9.761 44.758,9.199 45.45,9.199 45.677,9.426 46.524,9.426 48.479,7.471 48.479,7.435 48.814,7.099 49.281,7.099 49.852,7.67 50.456,7.67 50.56,7.774 51.124,7.774 LED91.A@51.147,7.75 ; LED31.A@34.347,16.15 34.077,16.15 33.85,15.923 33.089,15.923 32.247,15.082 32.247,14.575 32.239,14.567 32.239,14.058 LED43.A@32.247,14.05 32.256,14.042 32.764,14.042 32.773,14.05 33.384,14.05 34.495,15.16 v1(35.288,15.16) ; LED7.A@38.547,20.35 LED7.A@38.356,20.35 ; LED22.C@43.773,19.275 43.719,19.329 42.466,19.329 41.673,20.122 ; LED13.A@51.147,20.35 51.147,21.945 50.751,22.341 v1(48.126,22.341) 42.91,22.341 41.944,21.375 LED8.C@41.673,21.375 41.681,21.367 41.681,20.858 41.673,20.85 41.673,20.122 ; LED7.A@38.356,20.35 37.932,19.926 37.932,19.624 39.199,18.357 39.199,18.206 ; 39.199,18.206 39.243,18.25 40.122,18.25 40.131,18.258 40.639,18.258 LED21.A@40.647,18.25 40.975,18.578 40.975,19.424 41.673,20.122
  L3 w0.127: v1(26.463,6.129) 28.27,6.129 28.395,6.004 31.785,6.004 32.928,7.147 36.039,7.147 36.243,6.944 38.507,6.944 38.764,7.201 44.438,7.201 44.602,7.038 45.93,7.038 46.491,6.476 47.041,6.476 47.539,6.974 50.708,6.974 v2(51.263,7.529) ; v2(34.347,11.95) 34.347,14.22 v1(35.288,15.16)
  L8 w0.127: v1(48.126,22.341) 48.177,22.392 48.942,22.392 51.014,24.464 61.026,24.464 v3(61.045,24.483)
  BOTTOM_L10 w0.127: v3(61.045,24.483) 61.516,24.483 61.551,24.449 63.043,24.449 63.665,23.827 R108.1@63.665,23.575
  other v1: 51.263,7.529 34.347,11.95
  other v2: 26.463,6.129 35.288,15.16 48.126,22.341
  other v4: 61.045,24.483
  other v5: 48.126,22.341
ROW1_15: LED1.C LED2.A LED5.A LED6.C LED9.A LED10.C LED15.A LED16.C LED23.A LED24.C LED33.A LED34.C LED45.A LED46.C LED59.A LED60.C LED75.A LED76.C LED93.A LED94.C R195.1 | length 101.4
  TOP_L1 w0.127: LED1.C@26.973,21.375 27.022,21.375 LED2.A@28.047,20.35 LED2.A@28.056,20.342 ; LED93.A@28.047,5.65 28.047,5.825 v2(28.515,6.292) ; LED15.A@28.047,18.25 28.039,18.258 28.039,18.767 28.047,18.775 28.047,19.825 28.056,19.833 LED2.A@28.056,20.342 ; LED45.A@36.447,14.05 36.871,13.626 37.562,13.626 38.167,13.022 38.167,12.331 LED59.A@38.494,12.003 ; v2(37.473,21.375) 37.42,21.428 36.839,21.428 36.241,22.026 35.177,22.026 34.722,21.571 34.722,20.724 LED5.A@34.347,20.35 34.339,20.358 33.932,20.358 33.924,20.35 33.563,20.35 33.336,20.577 33.024,20.577 32.6,21.001 32.287,21.001 31.262,22.026 30.977,22.026 30.772,21.821 30.543,21.821 30.363,21.641 30.363,21.235 31.501,20.097 31.501,19.603 LED16.C@31.173,19.275 31.164,19.284 30.758,19.284 30.749,19.275 30.017,19.275 28.942,20.35 28.573,20.35 28.564,20.342 LED2.A@28.056,20.342 ; LED59.A@38.547,11.95 38.547,12.003 38.539,12.012 38.539,12.467 38.547,12.475 38.547,13.018 39.573,14.043 ; LED33.A@38.547,16.15 39.573,15.125 LED46.C@39.573,15.075 ; v2(41.673,12.975) 41.585,13.063 40.553,13.063 39.573,14.043 ; LED75.A@44.847,9.85 44.839,9.858 44.839,10.34 44.847,10.349 44.847,10.873 v1(45.041,11.067) 45.501,11.526 45.962,11.526 46.644,10.845 47.331,10.845 47.385,10.899 47.949,10.899 LED76.C@47.973,10.875 ; v1(47.24,21.306) 46.844,21.701 46.198,21.701 LED10.C@45.873,21.375 45.829,21.419 45.181,21.419 44.574,22.026 43.577,22.026 42.747,21.196 42.747,20.849 42.739,20.84 42.739,20.358 LED9.A@42.747,20.35 43.811,20.35 44.847,19.313 ; LED24.C@47.973,19.275 47.92,19.328 47.213,19.328 47.125,19.24 46.744,19.24 46.058,19.926 45.461,19.926 44.847,19.313 ; 39.573,14.043 39.573,14.55 39.581,14.558 39.581,15.067 LED46.C@39.573,15.075 ; LED46.C@39.573,15.075 39.996,15.499 40.843,15.499 41.345,16.001 41.345,16.848 LED34.C@41.673,17.175 41.681,17.167 42.19,17.167 42.198,17.175 43.032,17.175 43.684,16.524 43.988,16.524 44.424,16.96 44.424,17.826 LED23.A@44.847,18.25 44.839,18.258 44.839,18.74 44.847,18.749 44.847,19.313
  L3 w0.127: v1(28.077,18.286) 28.606,18.286 29.416,17.477 29.416,9.523 31.132,7.807 31.132,7.561 31.345,7.348 31.363,7.348 v1(31.363,6.429) 31.226,6.292 v2(28.515,6.292) ; v2(37.473,21.375) 39.104,19.744 40.436,19.744 41.047,20.356 v1(42.61,20.356) ; v2(41.673,12.975) 43.133,12.975 v1(45.041,11.067)
  L8 w0.127: v1(47.24,21.306) 47.758,21.824 48.891,21.824 51.243,24.176 v4(60.513,24.176)
  BOTTOM_L10 w0.127: v4(60.513,24.176) 60.992,24.176 61.019,24.149 62.243,24.149 62.665,23.727 R195.1@62.665,23.575
  other v1: 28.515,6.292 41.673,12.975 37.473,21.375
  other v2: 31.363,6.429 45.041,11.067 28.077,18.286 42.61,20.356 47.24,21.306
  other v3: 60.513,24.176
  other v5: 47.24,21.306
ROW2_15: LED3.C LED4.A LED5.C LED6.A LED11.A LED12.C LED17.A LED18.C LED25.A LED26.C LED35.A LED36.C LED47.A LED48.C LED61.A LED62.C LED77.A LED78.C LED95.A LED96.C R196.1 | length 122.3
  TOP_L1 w0.127: LED3.C@31.173,21.375 31.222,21.375 LED4.A@32.247,20.35 LED4.A@32.256,20.342 ; LED95.A@32.247,5.65 33.38,5.65 34.078,6.348 35.045,6.348 LED96.C@35.373,6.675 35.609,6.675 35.963,7.029 36.763,7.029 37.063,7.329 37.625,7.329 38.246,6.708 38.246,6.551 38.123,6.427 38.123,6.211 v2(38.113,6.201) ; LED17.A@32.247,18.25 32.239,18.258 32.239,18.767 32.247,18.775 32.247,19.825 32.256,19.833 LED4.A@32.256,20.342 ; v1(34.077,19.455) 34.11,19.455 34.192,19.373 35.275,19.373 LED18.C@35.364,19.284 ; v1@34.084,19.429 33.163,20.35 32.773,20.35 32.764,20.342 LED4.A@32.256,20.342 ; LED18.C@35.373,19.275 LED18.C@35.364,19.284 ; LED5.C@35.373,21.375 LED5.C@35.381,21.367 ; LED6.A@36.447,20.35 36.398,20.35 LED5.C@35.381,21.367 ; v2(40.586,14.098) 40.633,14.05 LED47.A@40.647,14.05 ; LED48.C@43.773,15.075 42.747,16.101 LED35.A@42.747,16.15 ; LED62.C@45.873,12.975 LED62.C@45.681,12.975 ; v1(46.863,19.529) 46.863,20.266 LED11.A@46.947,20.35 47.984,20.35 48.712,21.077 48.712,21.274 48.881,21.443 50.006,21.443 LED12.C@50.073,21.375 ; LED77.A@49.047,9.85 49.1,9.797 49.1,9.007 49.984,8.124 50.268,8.124 50.724,8.58 50.724,9.148 50.3,9.572 50.3,10.034 50.109,10.224 49.984,10.224 49.422,10.786 49.422,11.071 49.947,11.596 ; LED26.C@52.173,19.275 52.173,18.339 51.363,17.529 50.663,17.529 49.942,18.25 LED25.A@49.047,18.25 48.626,17.829 47.563,17.829 47.263,17.529 46.226,17.529 LED36.C@45.873,17.175 45.864,17.184 45.383,17.184 45.374,17.175 44.96,17.175 43.935,16.15 LED35.A@42.747,16.15 ; v2(53.026,7.847) 53.032,7.853 53.032,10.016 LED78.C@52.173,10.875 52.164,10.884 51.683,10.884 51.674,10.875 51.017,10.875 50.296,11.596 49.947,11.596 ; LED18.C@35.364,19.284 35.364,19.792 35.373,19.801 35.373,20.85 35.381,20.858 LED5.C@35.381,21.367 ; LED47.A@40.647,14.05 41.022,14.424 41.022,15.271 41.573,15.822 42.42,15.822 LED35.A@42.747,16.15 ; LED47.A@40.647,14.05 41.071,13.626 41.762,13.626 42.367,13.022 42.367,12.331 LED61.A@42.747,11.95 43.122,12.324 43.122,13.171 43.577,13.626 44.109,13.626 44.76,12.975 45.082,12.975 45.135,13.028 45.628,13.028 LED62.C@45.681,12.975 ; LED62.C@45.681,12.975 45.926,12.73 45.926,12.231 46.858,11.299 47.143,11.299 47.599,11.755 47.599,12.039 47.322,12.316 47.322,13.171 47.777,13.626 48.062,13.626 48.624,13.065 48.624,13.062 49.085,12.601 49.137,12.601 49.947,11.791 49.947,11.596
  L3 w0.127: v1(34.077,19.455) 33.808,19.187 33.808,17.172 34.406,16.574 36.718,16.574 37.063,16.229 37.063,14.329 37.295,14.098 v2(40.586,14.098) ; v2(38.113,6.201) 38.114,6.202 38.729,6.202 39.046,6.52 42.216,6.52 42.268,6.468 43.259,6.468 43.267,6.476 44.2,6.476 44.39,6.287 45.717,6.287 46.209,5.795 48.108,5.795 48.522,6.21 51.396,6.21 53.026,7.84 v2(53.026,7.847) ; v1(46.005,17.055) 46.863,17.913 v1(46.863,19.529)
  L8 w0.127: v1(46.863,19.529) 47.227,19.893 47.227,20.62 46.819,21.027 46.819,21.938 47.142,22.261 47.532,22.261 47.976,22.705 48.933,22.705 51.001,24.772 61.34,24.772 v4(61.525,24.957)
  BOTTOM_L10 w0.127: v4(61.525,24.957) 61.885,24.957 62.031,24.811 63.881,24.811 64.665,24.027 R196.1@64.665,23.575
  other v1: 38.113,6.201 53.026,7.847 40.586,14.098
  other v2: 46.005,17.055 34.077,19.455 46.863,19.529
  other v3: 61.525,24.957
  other v5: 46.863,19.529
ROW3_15: LED7.C LED8.A LED9.C LED10.A LED11.C LED12.A LED19.A LED20.C LED27.A LED28.C LED37.A LED38.C LED49.A LED50.C LED63.A LED64.C LED79.A LED80.C LED97.A LED98.C R197.1 | length 107.4
  TOP_L1 w0.127: v2(25.163,6.829) 25.163,5.129 25.52,4.772 34.706,4.772 35.263,5.329 35.856,5.329 36.109,5.582 36.383,5.582 LED97.A@36.447,5.517 ; v1(25.947,7.75) 25.939,7.758 25.939,8.267 25.947,8.275 25.947,8.917 26.683,9.653 27.36,9.653 28.238,8.775 28.649,8.775 28.658,8.784 29.064,8.784 v2(29.073,8.775) ; LED27.A@25.947,16.15 25.271,16.827 25.271,18.536 25.736,19.002 25.99,19.002 28.263,16.729 28.626,16.729 LED28.C@29.073,17.175 LED28.C@29.127,17.121 ; v1(29.075,16.877) 29.075,17.069 LED28.C@29.127,17.121 ; LED97.A@36.447,5.65 36.472,5.626 36.472,5.517 36.568,5.613 37.747,5.613 v1(37.763,5.629) ; LED19.A@36.447,18.25 v2(36.439,18.258) 35.931,18.258 35.922,18.25 35.302,18.25 35.106,18.053 35.083,18.053 34.605,17.575 34.245,17.575 34.054,17.385 34.054,17.11 33.468,16.524 32.696,16.524 31.291,17.929 31.08,17.929 30.522,17.371 30.522,16.801 30.799,16.524 30.799,15.955 30.222,15.378 30.012,15.378 29.496,15.894 29.496,16.752 LED28.C@29.127,17.121 ; v2(39.063,6.129) 39.573,6.639 LED98.C@39.573,6.675 ; v1(39.573,19.275) LED8.A@40.647,20.35 40.598,20.35 LED7.C@39.573,21.375 ; LED9.C@43.773,21.375 44.798,20.35 LED10.A@44.847,20.35 45.173,20.675 46.074,20.675 46.416,21.017 47.359,21.017 47.717,21.375 LED11.C@47.973,21.375 48.624,22.026 50.591,22.026 50.763,21.855 50.763,21.029 50.084,20.35 v1(49.047,20.35) 49,20.397 v1(49,21.154) ; LED49.A@44.847,14.05 46.101,14.05 46.799,14.748 47.645,14.748 ; LED63.A@46.947,11.95 46.947,13.204 47.645,13.901 ; LED37.A@46.947,16.15 46.947,16.101 LED50.C@47.973,15.075 ; LED64.C@50.073,12.975 49.032,12.975 48.851,13.156 48.851,13.159 48.156,13.853 48.153,13.853 48.106,13.901 47.645,13.901 ; v2(50.073,17.175) 49.745,16.848 48.899,16.848 48.396,16.345 48.396,15.499 LED50.C@47.973,15.075 ; 47.645,13.901 47.645,14.748 ; 47.645,14.748 LED50.C@47.973,15.075
  L3 w0.127: v2(25.163,6.829) 25.924,7.59 25.924,7.726 v1(25.947,7.75) ; v2(29.073,8.775) 29.073,16.874 v1(29.075,16.877) ; v2(36.439,18.258) 38.556,18.258 v1(39.573,19.275) 40.508,19.275 41.286,20.053 43.187,20.053 43.344,20.21 v1(44.863,20.21) ; v1(37.763,5.629) 38.563,5.629 v2(39.063,6.129) ; v1(49,21.154) 49.024,21.178 49.398,21.178 v5(49.434,21.214) ; v1(49.047,20.35) 49.047,18.201 v2(50.073,17.175)
  L8 w0.127: v5(49.434,21.214) 49.883,21.214 51.257,22.587 51.257,22.637 52.126,23.506 60.601,23.506 v3(60.612,23.517)
  BOTTOM_L10 w0.127: v3(60.612,23.517) 60.636,23.541 61.231,23.541 R197.1@61.265,23.575
  other v1: 39.063,6.129 25.163,6.829 29.073,8.775 50.073,17.175 36.439,18.258
  other v2: 37.763,5.629 25.947,7.75 29.075,16.877 39.573,19.275 44.863,20.21 49.047,20.35 49,21.154
  other v4: 60.612,23.517
ROW4_15: LED13.C LED14.A LED15.C LED16.A LED17.C LED18.A LED19.C LED20.A LED29.A LED30.C LED39.A LED40.C LED51.A LED52.C LED65.A LED66.C LED81.A LED82.C LED99.A LED100.C R198.1 | length 116.8
  TOP_L1 w0.127: v2(24.709,5.575) 24.709,6.949 25.163,7.403 ; LED14.A@25.947,18.25 25.956,18.242 25.956,17.835 25.947,17.826 25.947,17.245 26.973,16.219 26.973,15.601 26.964,15.592 LED40.C@26.964,15.084 ; LED66.C@26.973,10.875 26.599,10.501 25.163,10.501 ; LED40.C@26.973,15.075 LED40.C@26.964,15.084 ; LED29.A@30.147,16.15 30.139,16.158 30.139,16.667 30.147,16.675 30.147,17.725 30.156,17.733 LED16.A@30.156,18.021 ; LED82.C@33.273,8.775 33.264,8.784 32.858,8.784 32.849,8.775 32.276,8.775 31.406,9.645 31.196,9.645 30.522,8.971 30.522,8.124 LED81.A@30.147,7.75 30.139,7.758 29.631,7.758 29.622,7.75 29.363,7.75 28.989,8.124 28.568,8.124 27.266,9.426 26.777,9.426 26.322,8.971 26.322,8.306 26.599,8.029 26.599,7.364 26.163,6.929 25.638,6.929 25.163,7.403 ; LED17.C@33.273,19.275 33.322,19.275 LED18.A@34.347,18.25 ; LED20.A@38.547,18.25 38.498,18.25 LED19.C@37.473,19.275 37.464,19.284 36.956,19.284 36.947,19.275 36.219,19.275 35.568,18.624 34.722,18.624 LED18.A@34.347,18.25 ; v2(41.15,6.019) 41.127,5.996 40.993,5.996 LED99.A@40.647,5.65 41.456,4.841 47.111,4.841 47.723,4.229 52.063,4.229 53.063,5.229 53.063,7.119 53.434,7.49 53.434,10.958 52.442,11.95 LED65.A@51.147,11.95 51.147,12.845 49.942,14.05 LED51.A@49.047,14.05 49.047,15.213 49.984,16.15 50.649,16.15 50.657,16.158 51.139,16.158 LED39.A@51.147,16.15 ; v2(43.327,6.188) 43.773,6.634 LED100.C@43.773,6.675 ; LED52.C@52.173,15.075 51.992,15.256 51.303,15.945 LED39.A@51.147,16.15 ; LED13.C@52.173,21.375 52.173,20.319 52.824,19.668 52.824,16.698 52.65,16.524 51.522,16.524 LED39.A@51.147,16.15 ; 25.027,15.102 25.027,15.143 25.044,15.16 25.044,18.909 25.363,19.229 26.263,19.229 28.008,17.484 28.218,17.484 28.763,18.029 28.763,18.966 LED15.C@29.073,19.275 30.098,18.25 LED16.A@30.147,18.25 30.156,18.242 30.664,18.242 30.673,18.25 31.439,18.25 32.461,17.228 33.22,17.228 LED30.C@33.273,17.175 LED18.A@34.347,18.25 ; 25.027,15.102 25.027,13.01 24.929,12.912 24.929,11.538 24.923,11.532 24.923,11.169 25.163,10.929 25.163,10.501 ; 25.027,15.102 26.947,15.102 LED40.C@26.964,15.084 ; 25.163,7.403 25.163,10.501
  L3 w0.127: v2(24.709,5.575) 25.254,5.029 36.638,5.029 v5(36.65,5.041) ; v5@36.65,5.029 40.16,5.029 v2(41.15,6.019) 43.148,6.019 43.317,6.188 v2(43.327,6.188)
  BOTTOM_L10 w0.127: v5(36.65,5.041) 36.65,5.074 36.554,5.17 36.554,7.513 R198.1@37.039,7.998
  other v1: 24.709,5.575 41.15,6.019 43.327,6.188
  other v3: 36.65,5.041
  other v4: 36.65,5.041
ROW5_15: LED21.C LED22.A LED23.C LED24.A LED25.C LED26.A LED27.C LED28.A LED29.C LED30.A LED41.A LED42.C LED53.A LED54.C LED67.A LED68.C LED83.A LED84.C LED101.A LED102.C R199.1 | length 83.1
  TOP_L1 w0.127: LED53.A@25.947,11.95 25.939,11.958 25.939,12.467 25.947,12.475 25.947,13.117 26.755,13.925 27.522,13.925 27.646,14.05 LED41.A@28.047,14.05 ; LED27.C@26.973,17.175 27.022,17.175 LED28.A@28.047,16.15 LED28.A@28.056,16.142 ; LED67.A@28.047,9.85 28.087,9.811 28.722,9.811 v2(28.736,9.825) 29.017,9.543 29.349,9.543 29.693,9.199 30.429,9.199 31.226,9.996 LED68.C@31.226,10.822 ; v1(29.063,12.966) LED54.C@29.073,12.975 29.073,13.025 LED41.A@28.047,14.05 ; LED68.C@31.173,10.875 31.421,10.875 31.675,10.621 32.439,10.621 34.347,8.713 ; LED29.C@31.173,17.175 32.198,16.15 LED30.A@32.247,16.15 ; v1(34.339,7.721) 34.339,7.742 LED83.A@34.347,7.75 34.339,7.758 34.339,8.267 34.347,8.275 34.347,8.713 ; v1(34.433,17.191) 34.433,17.168 33.415,16.15 LED30.A@32.247,16.15 ; LED84.C@37.473,8.775 37.464,8.784 36.956,8.784 36.947,8.775 36.317,8.775 35.563,9.529 35.163,9.529 34.347,8.713 ; LED21.C@41.673,19.275 41.722,19.275 LED22.A@42.747,18.25 43.744,18.25 v2(44.47,18.977) ; v1(44.963,5.929) 44.847,5.813 LED101.A@44.847,5.65 44.868,5.629 v1(45.663,5.629) ; v1(45.873,19.275) 45.922,19.275 LED24.A@46.947,18.25 48.084,18.25 49.109,19.275 LED25.C@50.073,19.275 51.098,18.25 LED26.A@51.147,18.25 ; v2(47.836,5.507) 47.616,5.727 47.616,6.382 47.909,6.675 LED102.C@47.973,6.675 47.939,6.709 47.939,7.244 v2(47.958,7.263) ; LED41.A@28.047,14.05 28.039,14.058 28.039,14.567 28.047,14.575 28.047,15.625 28.056,15.633 LED28.A@28.056,16.142 ; LED28.A@28.056,16.142 28.564,16.142 28.573,16.15 28.919,16.15 29.994,15.075 30.749,15.075 30.758,15.084 31.164,15.084 LED42.C@31.173,15.075 LED30.A@32.247,16.15
  L2 w0.127: v2(28.777,13.019) 28.81,13.019 28.863,12.966 v1(29.063,12.966)
  L3 w0.127: v2(28.736,9.825) 28.756,9.846 28.756,12.998 v2(28.777,13.019) ; v1(34.339,7.721) 34.58,7.479 36.19,7.479 36.498,7.171 38.413,7.171 38.67,7.428 44.532,7.428 44.653,7.307 47.019,7.307 47.173,7.462 47.759,7.462 v2(47.958,7.263) ; v1(34.433,17.191) 43.266,17.191 44.47,18.395 v2(44.47,18.977) 44.769,19.275 v1(45.873,19.275) ; v1(45.663,5.629) 45.785,5.507 v2(47.836,5.507)
  BOTTOM_L10 w0.127: v1(32.705,10.382) 33.027,10.704 35.333,10.704 36.039,9.998 R199.1@36.039,7.998
  other v1: 47.836,5.507 47.958,7.263 28.736,9.825 44.47,18.977
  other v2: 45.663,5.629 34.339,7.721 32.705,10.382 34.433,17.191 45.873,19.275
  other v3: 32.705,10.382
  other v4: 32.705,10.382
  other v5: 45.663,5.629 32.705,10.382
